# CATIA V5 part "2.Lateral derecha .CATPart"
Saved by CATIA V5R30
Part number: 2.Lateral derecha 
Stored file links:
  C:\Users\valen\Desktop\Estandar CubeSat - Programa AVES-20220531T050024Z-001\Estandar CubeSat - Programa AVES\3D - MODELS\CATIA\2.Lateral derecha .CATPart

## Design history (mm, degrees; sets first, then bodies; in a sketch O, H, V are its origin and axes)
Set1
  Point1 "Point.1": stored without definition
Body1 "Sólido1" (main body)
  Solid1: solid without history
